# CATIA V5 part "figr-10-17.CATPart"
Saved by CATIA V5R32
Part number: Part1
Bounding box of the stored display mesh (mm): x -29.811 to 29.811, y 0 to 29.811, z -21.213 to 21.213
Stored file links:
  D:\PROJECTS\Project 2022\CATIA V5 6R 2022\Resources\Part Files\c10_catia_v5_6r2022_prt\c10_catia_v5_6r2022_prt\figr-10-17.CATPart
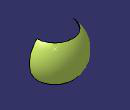
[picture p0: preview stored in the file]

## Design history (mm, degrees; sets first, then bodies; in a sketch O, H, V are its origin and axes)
Set1
  Point1: (0, 0, 0)
  Sphere1: Center Point1, Radius 30, Para1 -45, Para3 0, Para4 180
Body1 (main body)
